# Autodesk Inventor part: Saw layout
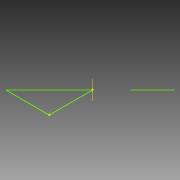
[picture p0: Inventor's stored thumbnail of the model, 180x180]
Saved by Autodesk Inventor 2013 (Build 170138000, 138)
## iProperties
Created: 2008-06
Part Number: Saw layout
Document SubType Name: Modeling
Designer: tangg
Density: 1 g/cm^3
Material: Generic
Author: tangg
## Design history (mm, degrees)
sketch "Sketch4"
  geometry: L1 (-82.286, -169.129)-(-38.592, -125.435); L2 (0, -86.843)-(86.843, 0); L3 (0, 0)-(0, -86.843); L4 (0, 0)-(86.843, 0)
  constraints: 8 end point
workpoint "Work Point4"
  workaxis "Work Axis2"
workplane "Work Plane2"
other parameters: "d1" = 45 deg
